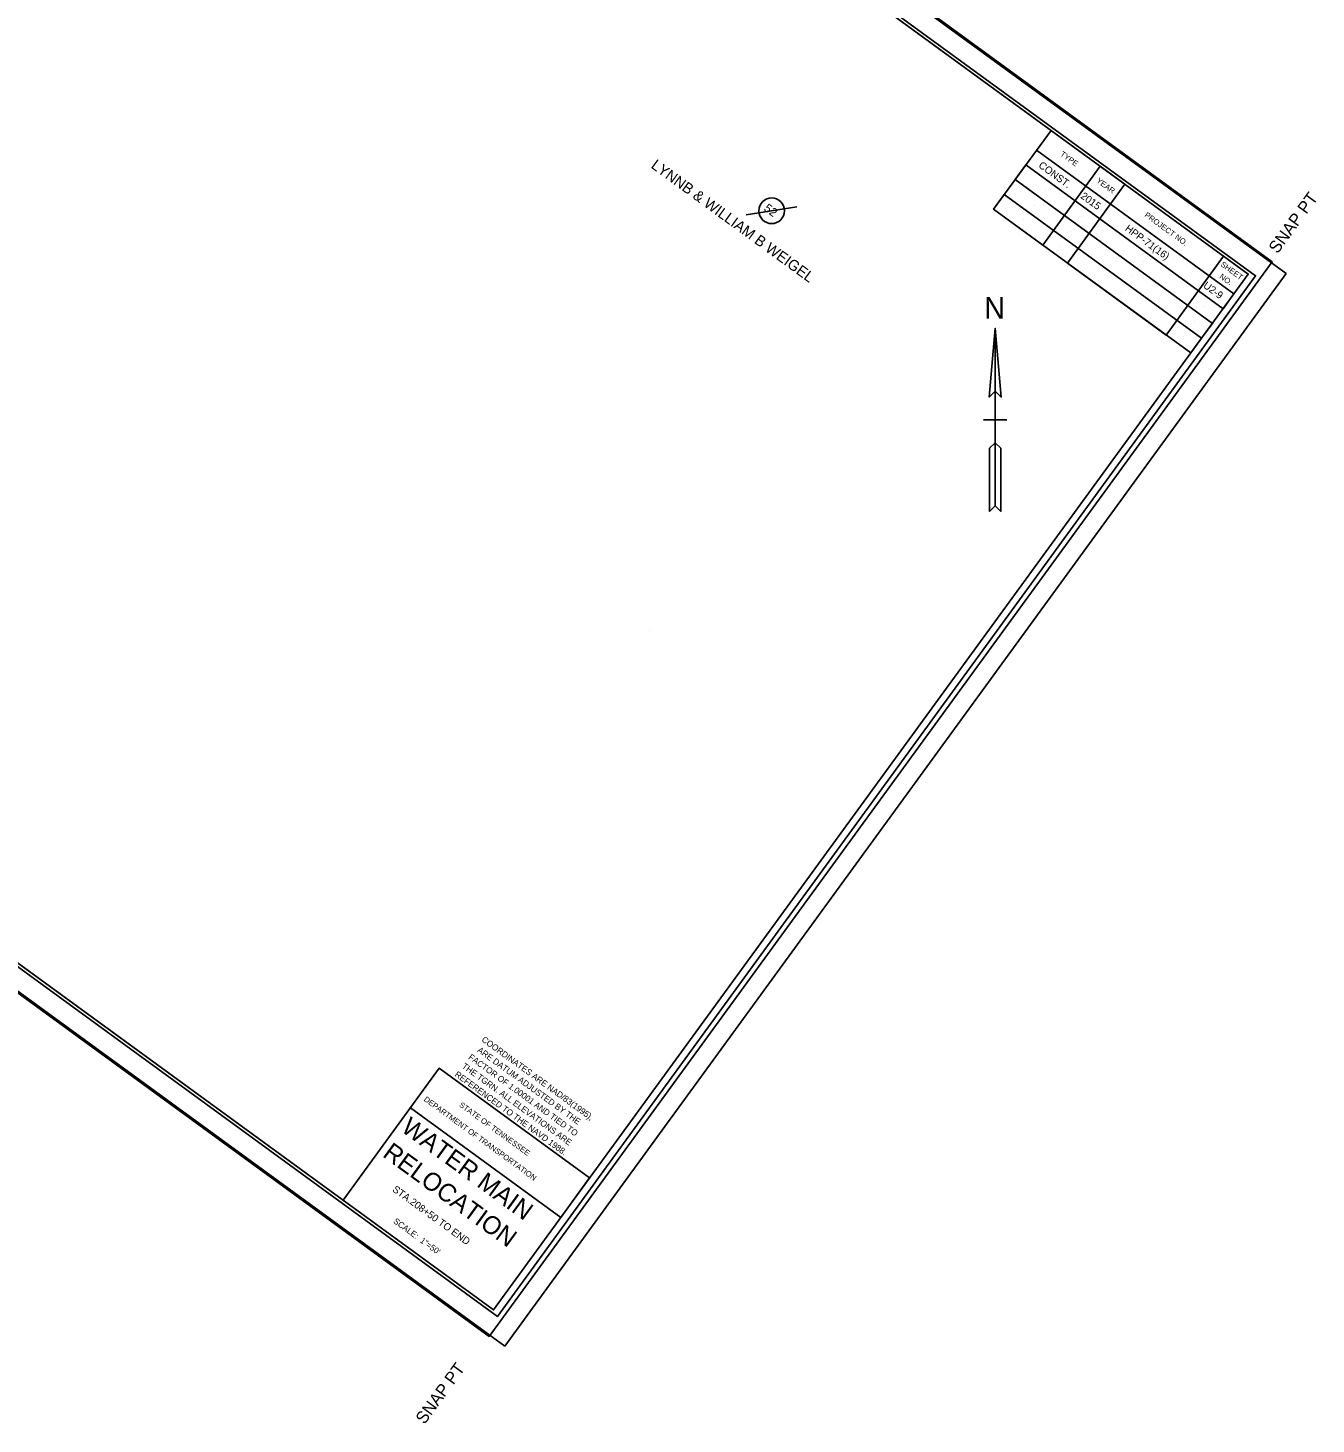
# Model space of a CAD drawing. Extents: x 2632015 to 2634135, y 566161 to 568172.
# Drawn here: x 2633079 to 2634135, y 566161 to 567305 of the extents above; entities that cross this region are included whole.
import ezdxf

# ---------------------------------------------------------------- set-up
doc = ezdxf.new("R2010")
doc.units = 0
for name, color, linetype in [('DESIGN - CENTERLINE - Proposed Text', 7, 'Continuous'), ('DESIGN - SCRATCH - User 1', 7, 'Continuous'), ('DESIGN - SHEET - Corner Text', 7, 'Continuous'), ('DESIGN - SHEET - Light Grid', 7, 'Continuous'), ('DESIGN - SHEET - Linework', 7, 'Continuous'), ('DESIGN - SHEET - Plot Shape', 7, 'Continuous'), ('SURVEY - PROPERTY - Owners', 7, 'Continuous'), ('SURVEY - PROPERTY - Tract Numbers', 7, 'Continuous')]:
    doc.layers.add(name, color=color, linetype=linetype)

msp = doc.modelspace()

# ---------------------------------------------------------------- linework, layer by layer
at = {"layer": 'DESIGN - CENTERLINE - Proposed Text'}
for p, q in [((2633871.9, 566983.6), (2633862.4, 566983.6)), ((2633881.3, 566983.6), (2633871.9, 566983.6))]:
    msp.add_line(p, q, dxfattribs=at)
msp.add_lwpolyline([(2633871.9, 567058.6), (2633867, 567002.3), (2633871.9, 567007.2), (2633876.8, 567002.3), (2633871.9, 567058.6), (2633871.9, 566913.1), (2633876.4, 566908.6), (2633876.4, 566960.3), (2633871.9, 566964.9), (2633867.3, 566960.3), (2633867.3, 566908.6), (2633871.9, 566913.1)], dxfattribs=at)
for points in [[(2633871.9, 567007.2), (2633876.8, 567002.3), (2633871.9, 567058.6)], [(2633867.3, 566908.6), (2633871.9, 566913.1), (2633871.9, 566964.9), (2633867.3, 566960.3)]]:
    msp.add_lwpolyline(points, close=True, dxfattribs=at)
at = {"layer": 'DESIGN - SCRATCH - User 1'}
for p, q in [((2633921.6, 567183.9), (2633921.6, 567183.9)), ((2633912.8, 567171.7), (2633912.8, 567171.7)), ((2633903.9, 567159.6), (2633903.9, 567159.6)), ((2633951.5, 567162.1), (2633951.5, 567162.1)), ((2633942.7, 567149.9), (2633942.7, 567149.9)), ((2633895.1, 567147.5), (2633895.1, 567147.5)), ((2633933.8, 567137.8), (2633933.8, 567137.8)), ((2633925, 567125.7), (2633925, 567125.7)), ((2634002, 567125.3), (2634002, 567125.3)), ((2633993.2, 567113.1), (2633993.2, 567113.1)), ((2633984.3, 567101), (2633984.3, 567101)), ((2633975.5, 567088.9), (2633975.5, 567088.9)), ((2634052.5, 567088.5), (2634052.5, 567088.5)), ((2634043.7, 567076.3), (2634043.7, 567076.3)), ((2634034.8, 567064.2), (2634034.8, 567064.2)), ((2634026, 567052.1), (2634026, 567052.1)), ((2633588.8, 566810.8), (2633588.8, 566810.8)), ((2633426.8, 566337.2), (2633426.8, 566337.2))]:
    msp.add_line(p, q, dxfattribs=at)
at = {"layer": 'DESIGN - SHEET - Light Grid'}
msp.add_lwpolyline([(2632118.4, 567229.6), (2633464, 566249), (2634085.3, 567101.7), (2632739.7, 568082.2)], close=True, dxfattribs=at)
at = {"layer": 'DESIGN - SHEET - Linework'}
for p, q in [((2632655.7, 568163.5), (2634110.4, 567103.4)), ((2632015.3, 567284.7), (2633470, 566224.6)), ((2634110.4, 567103.4), (2633470, 566224.6))]:
    msp.add_line(p, q, dxfattribs=at)
for points in [[(2632807, 568030.1), (2632188.6, 567181.6), (2633460.8, 566254.4), (2634079.2, 567103), (2632807, 568030.1)], [(2633917.6, 567220.8), (2633870.5, 567156.2), (2634032.1, 567038.4), (2634079.2, 567103), (2634059, 567117.7), (2634011.9, 567053.1), (2633931.1, 567112), (2633978.2, 567176.6), (2633958, 567191.4), (2633910.9, 567126.7), (2633870.5, 567156.2), (2633879.3, 567168.3), (2634040.9, 567050.5), (2634049.8, 567062.6), (2633888.1, 567180.4), (2633897, 567192.5), (2634058.6, 567074.7), (2634067.4, 567086.9), (2633905.8, 567204.6)], [(2633337.6, 566344.3), (2633416.3, 566452.3), (2633539.5, 566362.5), (2633516, 566330.1), (2633392.7, 566419.9)]]:
    msp.add_lwpolyline(points, dxfattribs=at)
at = {"layer": 'DESIGN - SHEET - Plot Shape'}
for points in [[(2632724.9, 568114.3), (2634098.8, 567113.1), (2633457.2, 566232.7), (2632083.3, 567233.9)], [(2632738.3, 568080.2), (2634079.2, 567103), (2633460.8, 566254.4), (2632119.9, 567231.6)]]:
    msp.add_lwpolyline(points, close=True, dxfattribs=at)
at = {"layer": 'SURVEY - PROPERTY - Tract Numbers'}
msp.add_line((2633667.9, 567151.6), (2633709.4, 567158.1), dxfattribs=at)
msp.add_circle((2633688.7, 567154.9), 10.5, dxfattribs=at)

# ---------------------------------------------------------------- texts
at = {"layer": 'DESIGN - CENTERLINE - Proposed Text'}
msp.add_text('N', height=17.7, dxfattribs=at).set_placement((2633862.8, 567066.6))
at = {"layer": 'DESIGN - SHEET - Corner Text'}
for s, height, rotation, p in [('CONST.', 6, 323.918, (2633906.8, 567191)), ('TYPE', 4.5, 323.918, (2633924.7, 567200.5)), ('YEAR', 4.5, 323.918, (2633954.3, 567178.7)), ('  SNAP PT', 10, 53.918, (2634098.8, 567113.1)), ('2015', 6, 323.918, (2633941.3, 567165.8)), ('PROJECT NO.', 4.5, 323.918, (2633993.8, 567150.5)), ('HPP-71(16)', 6, 323.918, (2633977.7, 567139.2)), ('NO.', 4.5, 323.918, (2634055.2, 567100.1)), ('SHEET', 4.5, 323.918, (2634056.1, 567110.1)), ('U2-9', 6, 323.918, (2634041.8, 567092.5)), ('COORDINATES ARE NAD/83(1995),', 5, 323.918, (2633450.5, 566474.8)), ('FACTOR OF 1.00001 AND TIED TO', 5, 323.918, (2633439.7, 566460.4)), ('ARE DATUM ADJUSTED BY THE', 5, 323.918, (2633447, 566466.2)), ('THE TGRN. ALL ELEVATIONS ARE', 5, 323.918, (2633434.4, 566453.1)), ('REFERENCED TO THE NAVD 1988.', 5, 323.918, (2633428.5, 566446.3)), ('DEPARTMENT OF TRANSPORTATION', 4.5, 323.918, (2633403.2, 566426)), ('STATE OF TENNESSEE', 4.5, 323.918, (2633432.2, 566421.4)), ('WATER MAIN', 14.76, 323.918, (2633384.2, 566401.3)), ('RELOCATION', 14.76, 323.918, (2633369.1, 566380.5)), ('STA.208+50 TO END', 5.905, 323.918, (2633377.4, 566352)), ('SCALE:  1"=50\'', 4.921, 323.918, (2633378.2, 566326.1)), ('SNAP PT  ', 10, 53.918, (2633404.2, 566160))]:
    msp.add_text(s, height=height, rotation=rotation, dxfattribs=at).set_placement(p)
at = {"layer": 'SURVEY - PROPERTY - Owners'}
msp.add_text('LYNNB & WILLIAM B WEIGEL', height=8.75, rotation=323.918, dxfattribs=at).set_placement((2633589.2, 567190.6))
at = {"layer": 'SURVEY - PROPERTY - Tract Numbers'}
msp.add_text('52', height=7, rotation=323.918, dxfattribs=at).set_placement((2633681.7, 567155.6))

doc.saveas('drawing.dxf')
